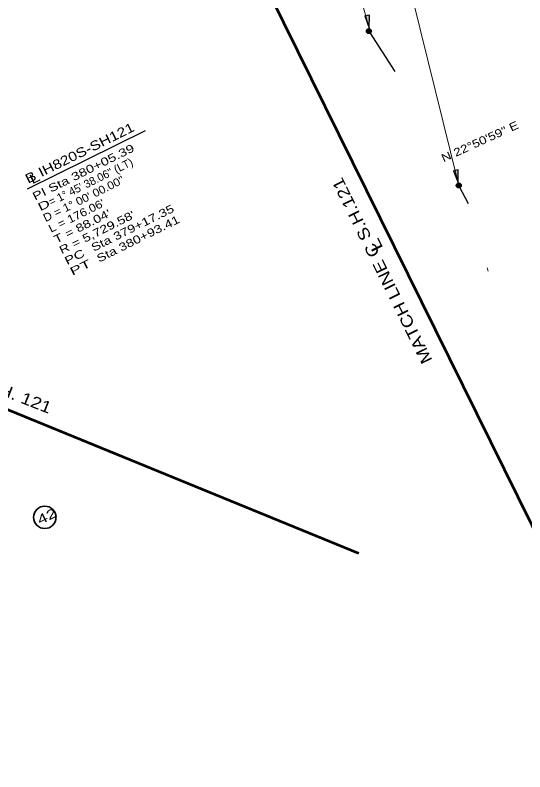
# Model space of a CAD drawing. Extents: x 2356431 to 2371438, y 6972864 to 6982525.
# Drawn here: x 2365063 to 2365828, y 6978894 to 6980028 of the extents above; entities that cross this region are included whole.
import ezdxf
from ezdxf.enums import TextEntityAlignment as Align

# ---------------------------------------------------------------- set-up
doc = ezdxf.new("R2010")
doc.units = 0
doc.header["$LTSCALE"] = 5.6
for name, color, linetype, lineweight in [('1', 7, 'Continuous', 25), ('17', 7, 'Continuous', 35), ('2', 7, 'Continuous', 35), ('28', 7, 'Continuous', 35), ('48', 7, 'Continuous', 25), ('61', 7, 'Continuous', 13)]:
    doc.layers.add(name, color=color, linetype=linetype, lineweight=lineweight)
doc.layers.add('33', color=7, linetype='Continuous')

msp = doc.modelspace()

# ---------------------------------------------------------------- hatches: boundary and pattern name
at = {"layer": '1'}
for points in [[(2365593.998, 6980008.645), (2365594.742, 6980028.163), (2365587.623, 6980027.11)], [(2365597.266, 6980004.751, 1), (2365589.842, 6980003.984, 1)], [(2365727.493, 6979776.865), (2365727.643, 6979796.397), (2365720.559, 6979795.128)], [(2365732.107, 6979773.024, 1), (2365724.644, 6979772.97, 1)]]:
    msp.add_hatch(color=256, dxfattribs=at).paths.add_polyline_path(points)

# ---------------------------------------------------------------- linework, layer by layer
at = {"layer": '1', "lineweight": 53}
for p, q in [((2365274.698, 6980404.566), (2366089.834, 6978752.959)), ((2365578.634, 6979221.374), (2364090.226, 6979829.17))]:
    msp.add_line(p, q, dxfattribs=at)
at = {"layer": '1', "lineweight": 13}
for p, q in [((2365593.998, 6980008.645), (2365486.909, 6980397.919)), ((2365727.493, 6979776.865), (2365614.297, 6980235.555))]:
    msp.add_line(p, q, dxfattribs=at)
at = {"layer": '1'}
for p, q in [((2365594.479, 6980002.821), (2365632.64, 6979943.623)), ((2365729.148, 6979771.369), (2365742.41, 6979745.699))]:
    msp.add_line(p, q, dxfattribs=at)
for points in [[(2365593.998, 6980008.645), (2365594.742, 6980028.163), (2365587.623, 6980027.11)], [(2365727.493, 6979776.865), (2365727.643, 6979796.397), (2365720.559, 6979795.128)]]:
    msp.add_lwpolyline(points, close=True, dxfattribs=at)
for centre in [(2365593.554, 6980004.368), (2365728.375, 6979772.997)]:
    msp.add_circle(centre, 3.732, dxfattribs=at)
at = {"layer": '17'}
msp.add_circle((2365107.495, 6979275.362), 16.828, dxfattribs=at)
at = {"layer": '2', "lineweight": 13}
msp.add_line((2365770.806, 6979649.431), (2365772.469, 6979644.714), dxfattribs=at)
at = {"layer": '61', "lineweight": 25}
msp.add_line((2365081.847, 6979767.844), (2365258.804, 6979855.179), dxfattribs=at)

# ---------------------------------------------------------------- texts
at = {"layer": '1'}
for s, width, p in [('MATCH LINE C S.H.121', 1.2, (2365621.221, 6979648.832)), ('L', 1.4, (2365611.376, 6979687.404))]:
    msp.add_text(s, height=17.5, rotation=116.268, dxfattribs=dict(at, width=width)).set_placement(p, align=Align.CENTER)
at = {"layer": '17', "width": 1.45}
msp.add_text('42', height=14, rotation=26.268, dxfattribs=at).set_placement((2365113.79, 6979270.662), align=Align.CENTER)
at = {"layer": '28', "width": 1.25}
for s, height, rotation, p in [('N 22°50\'59" E', 12, 24.43, (2365762.584, 6979833.353)), ('B IH820S-SH121 ', 14, 26.377, (2365165.896, 6979816.921))]:
    msp.add_text(s, height=height, rotation=rotation, dxfattribs=at).set_placement(p, align=Align.CENTER)
at = {"layer": '33'}
for s, width, p in [('PI Sta 380+05.39', 1.35, (2365092.831, 6979750.212)), ('D = 1° 00\' 00.00"', 1.1, (2365108.859, 6979718)), ('D', 1.55, (2365100.845, 6979734.105)), ("L = 176.06'", 1.15, (2365116.872, 6979701.893)), ('Sta 379+17.35', 1.3, (2365180.889, 6979673.497)), ("T = 88.04'", 1.3, (2365124.886, 6979685.787)), ("R = 5,729.58'", 1.3, (2365132.9, 6979669.68)), ('Sta 380+93.41', 1.3, (2365189.027, 6979657.14)), ('PC', 1.4, (2365140.914, 6979653.574)), ('PT', 1.6, (2365148.927, 6979637.467))]:
    msp.add_text(s, height=12, rotation=26.452, dxfattribs=dict(at, width=width)).set_placement(p)
msp.add_text('= 1° 45\' 38.06" (LT)', height=12, rotation=26.452, dxfattribs=at).set_placement((2365116.961, 6979742.124))
at = {"layer": '48', "width": 1.2}
msp.add_text('MATCH LINE C S.H. 121', height=17.5, rotation=338.655, dxfattribs=at).set_placement((2364966.69, 6979487.826), align=Align.CENTER)
at = {"layer": '61', "width": 1.4}
msp.add_text('L', height=14, rotation=26.268, dxfattribs=at).set_placement((2365095.34, 6979777.951), align=Align.CENTER)

doc.saveas('drawing.dxf')
